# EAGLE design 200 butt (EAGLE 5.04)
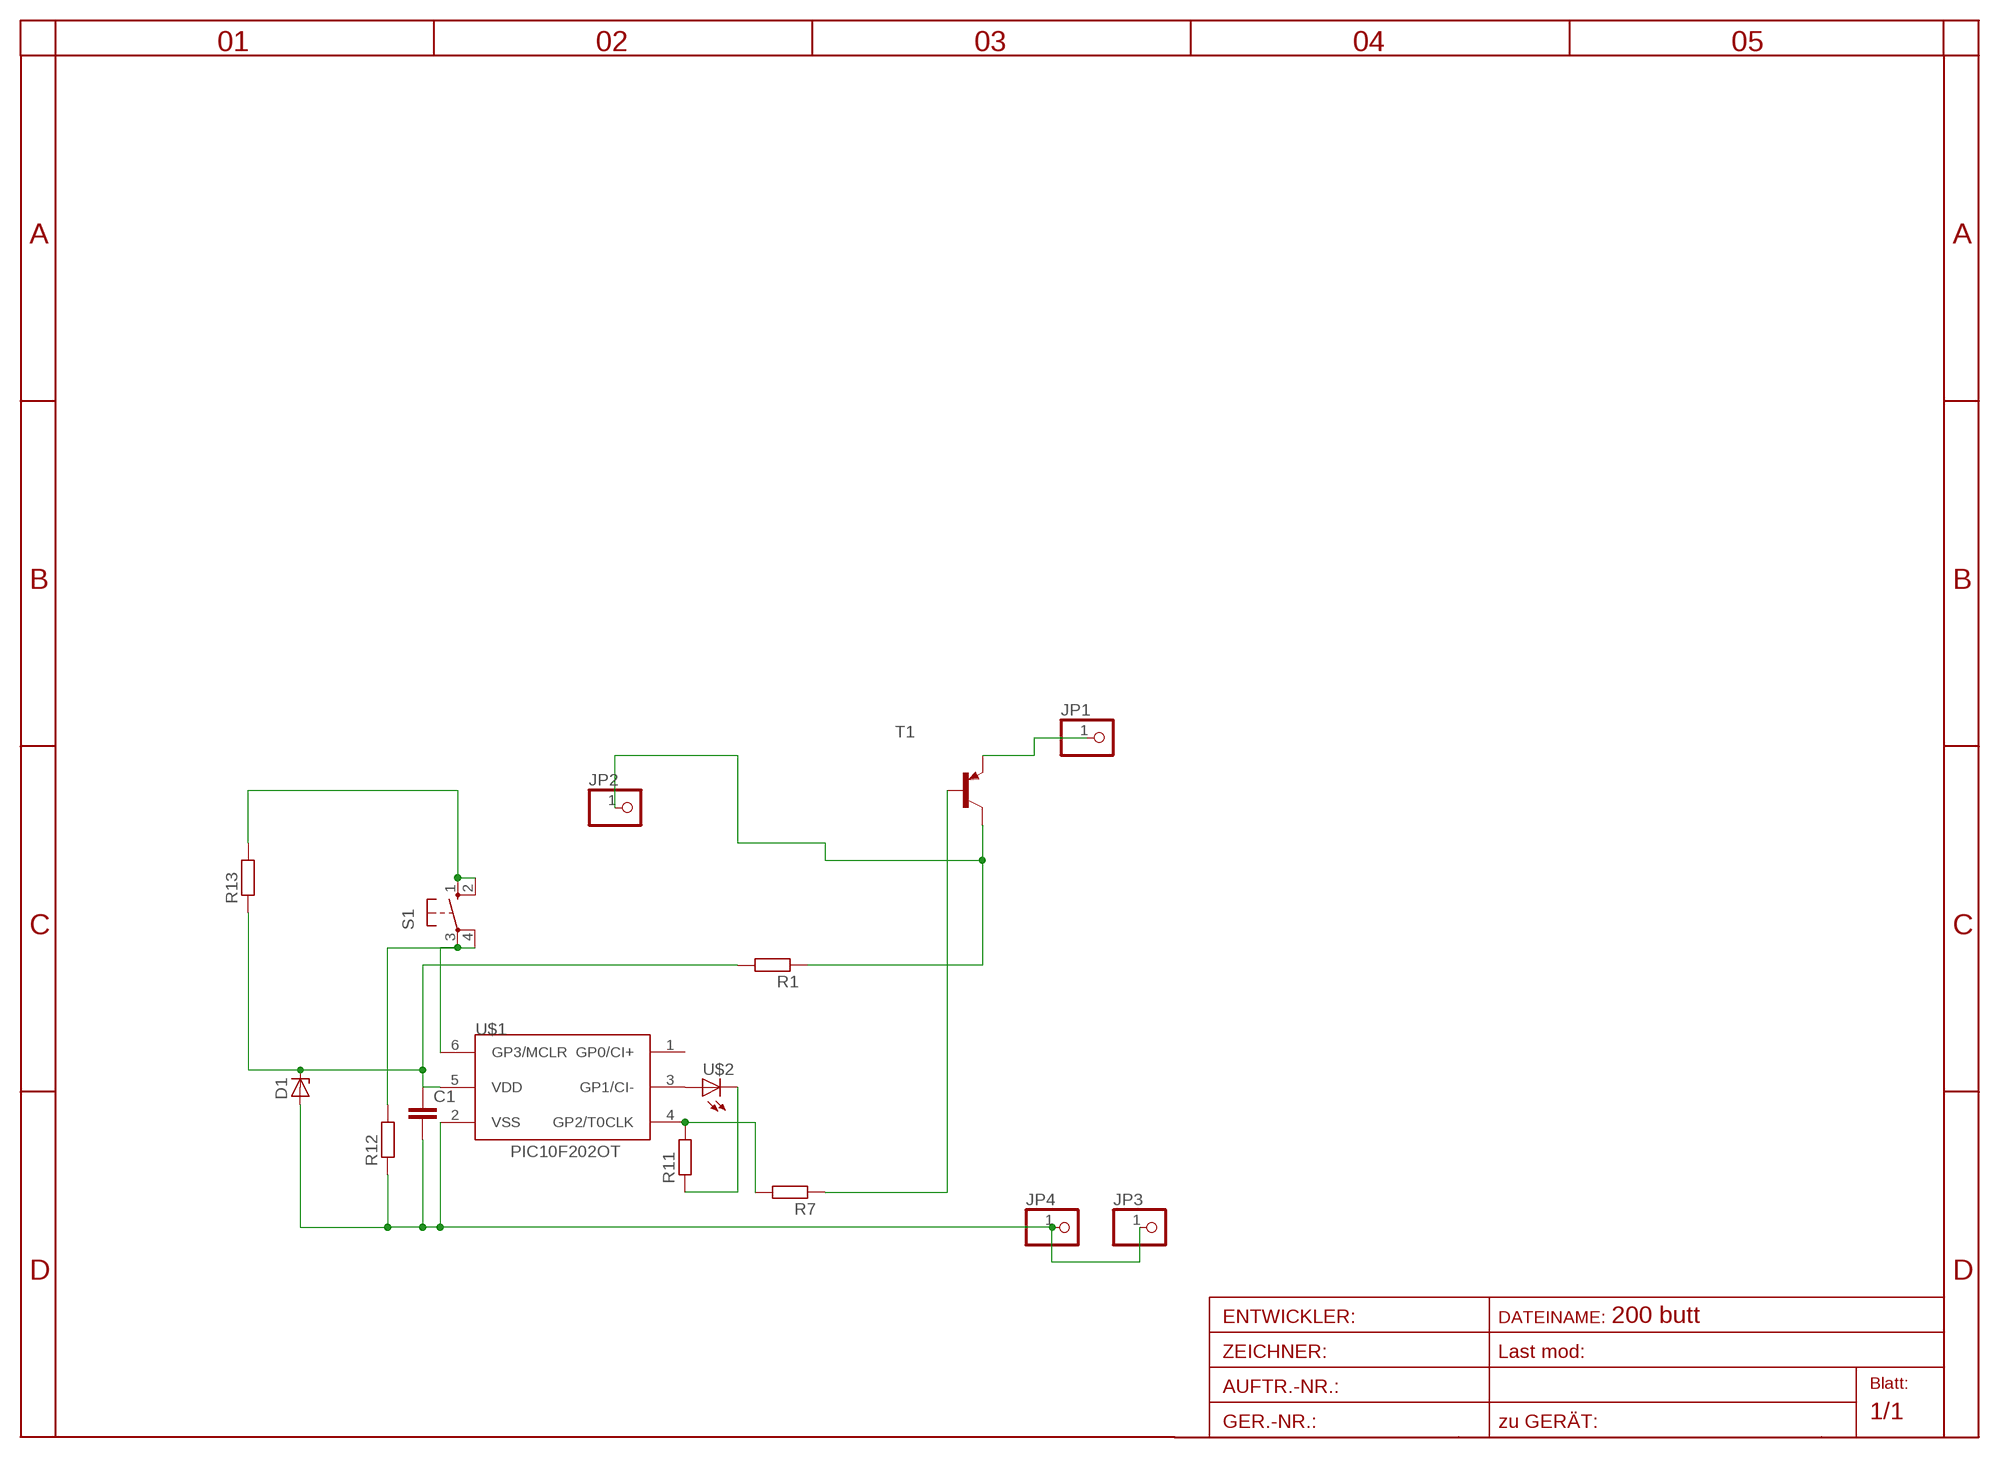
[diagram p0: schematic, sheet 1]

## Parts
C1  C-EUC1206  [C1206]
D1  ZENER-DIODESOD80C  [SOD80C]
JP1  PINHD-1X1  [1X01]
JP2  PINHD-1X1  [1X01]
JP3  PINHD-1X1  [1X01]
JP4  PINHD-1X1  [1X01]
R1  R-EU_R0805  [R0805]
R7  R-EU_R0805  [R0805]
R11  R-EU_R0805  [R0805]
R12  R-EU_R0805  [R0805]
R13  R-EU_R0805  [R0805]
S1  10-XX  [B3F-10XX]
T1  -PNP-SOT23-BCE  [SOT23-BCE]
U$1  PIC10F202OT  [SOT23-6]
U$2  LED3MM  [LED3MM]

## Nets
GND: C1.2 D1.A JP3.1 JP4.1 R12.1 U$1.2(VSS)
N$5: U$1.3(GP1/CI-) U$2.A
N$6: R11.1 U$2.K(C)
N$9: R7.2 R11.2 U$1.4(GP2/T0CLK)
N$10: R7.1 T1.B
N$11: R12.2 S1.3(P) S1.4(P1) U$1.6(GP3/MCLR)
N$15: R13.2 S1.1(S) S1.2(S1)
V+IN: JP2.1 R1.1 T1.C
V+OUT: JP1.1 T1.E
VDD: C1.1 D1.C R1.2 R13.1 U$1.5(VDD)
Unconnected: U$1.1(GP0/CI+)

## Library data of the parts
C1 = rcl:C-EU: CAPACITOR, European symbol
D1 = diode-1:ZENER-DIODE: Z-Diode
JP1-JP4 = pinhead:PINHD-1X1: PIN HEADER
R1 R7 R11-R13 = rcl:R-EU_: RESISTOR, European symbol
S1 = switch-omron:10-XX: OMRON SWITCH
T1 = transistor:*-PNP-: PNP Transistror
U$1 = microchip-5:PIC10F2*: uPC nW 0,25/0,5k Program Flash memory Comparator
U$2 = led(2):LED: LED

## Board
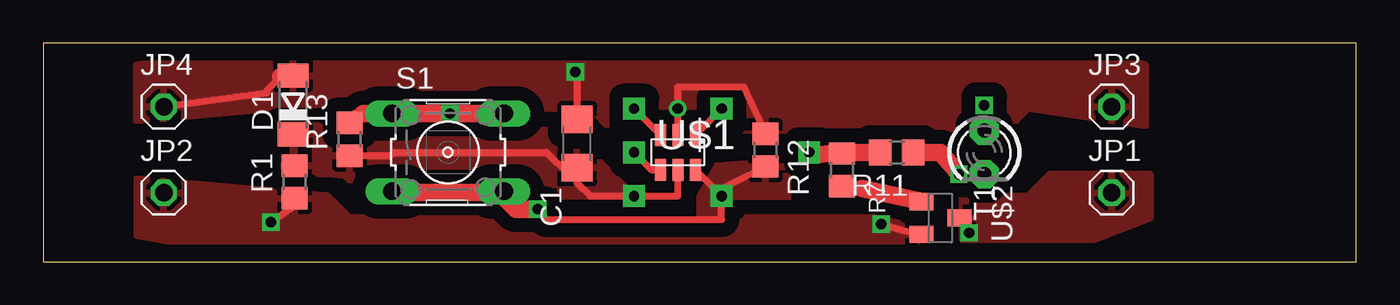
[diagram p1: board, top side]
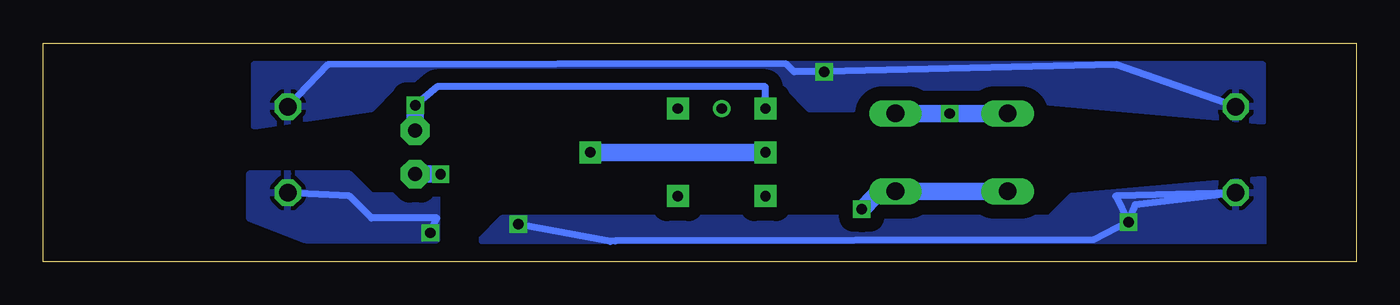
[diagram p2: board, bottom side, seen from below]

Size 76.2 x 12.7 mm. Coordinates in mm from the lower left corner, seen from the top.
Outline: 0,0 76.2,0 76.2,12.7 0,12.7 0,0
Copper layers (1*16): Top 0.035mm / dielectric 1.5mm / Bottom 0.035mm
Design rules "default": minimum track width 10mil, minimum drill 24mil, track to track 8mil, track to pad 8mil, pad to pad 8mil, via to via 8mil, smd to smd 8mil, copper to edge 40mil, drill to drill 8mil, minimum pad ring 10mil, minimum via ring 8mil, stop-mask expansion 4mil, vias tented up to drill 0mil, thermal gap 10mil

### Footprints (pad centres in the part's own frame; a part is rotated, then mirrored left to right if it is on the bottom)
C1206 = smd 1.6 x 1.8: 1 -1.4,0; 2 1.4,0
SOD80C = smd 1.4 x 1.8: A 1.7,0; C -1.7,0
1X01 = drill 1.016 octagon: 1 0,0
R0805 = smd 1.3 x 1.5: 1 -0.95,0; 2 0.95,0
B3F-10XX = drill 1.016 long: 1 -3.251,2.261; 2 3.251,2.261; 3 -3.251,-2.261; 4 3.251,-2.261
SOT23-BCE = smd 1 x 1.4: B -0.95,-1.1; C 0.95,-1.1; E 0,1.1
SOT23-6 = smd 0.635 x 1.27: 1 -1.016,-1.016; 2 0,-1.016; 3 1.016,-1.016; 4 1.016,1.016; 5 0,1.016; 6 -1.016,1.016
LED3MM = drill 0.813 pad 1.676 octagon: A -1.27,0; K 1.27,0

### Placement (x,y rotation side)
C1  30.99,6.86 90 top
D1  14.5,9.1 90 top
JP1  62,4 0 top
JP2  7,4 0 top
JP3  62,9 0 top
JP4  7,9 0 top
R1  14.59,4.63 90 top
R7  46.35,5.33 90 top
R11  49.53,6.35 180 top
R12  41.91,6.48 270 top
R13  17.78,7.11 90 top
S1  23.5,6.35 0 top
T1  52.07,2.54 270 top
U$1  36.83,6.35 180 top
U$2  54.61,6.35 270 top

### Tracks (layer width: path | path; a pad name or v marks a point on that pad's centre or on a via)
GND  (via drill 0.6, 0.6 pad 0.61)
  Top 0.406: R12.1 40.64,10.16 36.83,10.16 v36.83,8.89 U$1.2 | C1.2 30.99,10.92 v30.88,11.03 | 13.78,10.75 12.99,9.96 12.99,9.82 JP4.1
  Top 1.016: 13.78,10.75 D1.A
  Bottom 0.406: JP3.1 59.69,11.43 33.1,11.5 32.63,11.03 v30.88,11.03 13.97,11.43 JP4.1
  pour Top (isolate 0.813, rank 2): 5.43,8.16 5.43,11.43 12.7,12.7 59.69,12.7 63.96,11.43 63.96,7.89 57.15,8.89 55.88,7.62 33.02,7.62 31.75,8.89 29.21,8.89 27.94,10.16
  pour Bottom (isolate 0.813, rank 2): 5.43,8.16 5.43,11.43 12.7,12.7 59.69,12.7 63.96,11.43 63.96,7.89 57.15,8.89 55.88,10.16 33.02,10.16 31.75,8.89 29.21,8.89 27.94,10.16
N$1  (via drill 0.6 pad 1.27)
  Top 0.406: v39.37,8.89 38.1,7.62
N$5  (via drill 0.6, 0.6 pad 1.27)
  Top 0.406: U$1.3 v34.29,8.89
  Bottom 0.406: U$2.A v54.61,9.09 53.34,10.16 34.29,10.16 v34.29,8.89
  Bottom 1.016: v54.61,9.09 U$2.A
N$6  (via drill 0.6)
  Top 0.406: R11.1 51.12,6.35
  Top 1.016: v53.14,5.08 52.07,6.35 51.12,6.35
  Bottom 1.016: v53.14,5.08 U$2.K
N$9  (via drill 0.6 pad 1.27)
  Top 0.406: R7.2 46.92,6.35 | v44.45,6.35 44.32,6.22 | U$1.4 35.31,5.33 v34.29,6.35
  Top 1.016: 46.92,6.35 R11.2 | 44.32,6.22 R7.2
  Bottom 1.016: v34.29,6.35 v44.45,6.35
N$10
  Top 0.406: R7.1 47.5,4.25
  Top 1.016: 47.5,4.25 T1.B
N$11  (via drill 0.6, 0.6 pad 1.27)
  Top 0.406: 39.37,4.26 v39.37,3.81 39.37,2.44 29.21,2.44 v28.7,3.05 | 39.37,4.26 R12.2 | 39.37,4.26 38.92,4.26 U$1.6 | S1.3 20.32,4.01
  Top 1.016: 20.32,4.01 26.47,4.01 27.43,3.05 v28.7,3.05
  Bottom 0.406: 27.94,3.81 26.67,3.81
  Bottom 1.016: S1.3 S1.4 | v28.7,3.05 27.94,3.81
  pour Top (isolate 0.813, rank 4): 39.12,5.59 42.67,5.84 43.18,5.08 43.18,2.54 38.1,2.54 38.1,3.81
N$15  (via drill 0.6)
  Top 0.406: R13.2 18.58,8.59 18.06,8.61 S1.1
  Top 1.016: 18.58,8.59 27.27,8.59
  Bottom 0.406: v23.6,8.6 26,8.5 26,8.89 26.75,8.89 S1.2
  Bottom 1.016: S1.1 S1.2
V+IN  (via drill 0.6)
  Top 0.406: T1.C 50.8,1.59 v48.63,2.17 | R1.1 14.41,3.11 v13.22,2.3
  Bottom 0.406: v13.22,2.3 13.97,3.81 JP2.1 12.83,3.3 v13.22,2.3 | v13.22,2.3 15.24,1.27 43,1.2 43.3,1.17 v48.63,2.17
  pour Top (isolate 0.813, rank 2): 5.43,4.81 5.43,1.54 13.97,0 49.53,0 50.8,1.27 49.53,2.54 17.78,2.54 16.51,3.81
  pour Bottom (isolate 0.813, rank 2): 5.43,4.81 5.43,0.54 13.97,0 49.53,0 50.8,1.27 49.53,2.54 17.78,2.54 16.51,3.81
V+OUT  (via drill 0.6)
  Top 0.406: T1.E v53.74,1.67
  Bottom 0.406: v53.74,1.67 53.34,2.54 57.15,2.54 58.42,3.81 JP1.1
  pour Top (isolate 0.813, rank 3): 53.34,3.81 57.15,3.81 58.42,5.08 64.23,5.08 64.23,2.54 60.96,1.27 53.34,1.27
  pour Bottom (isolate 0.813, rank 3): 53.34,3.81 57.15,3.81 58.42,5.08 64.23,5.08 64.23,2.54 60.96,1.27 53.34,1.27
VDD  (via drill 0.6 pad 1.27)
  Top 0.406: U$1.5 36.83,3.81 v34.29,3.81 31.75,3.81 30.99,4.57 C1.1 30.61,5.08 30.48,5.08 29.21,6.35 20.32,6.35 20.13,6.16 R13.1
  pour Top (isolate 0.813, rank 3): 13.97,8.89 13.97,3.81 34.29,3.81 31.75,6.35 30.48,6.35 29.21,7.62 16.51,7.62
